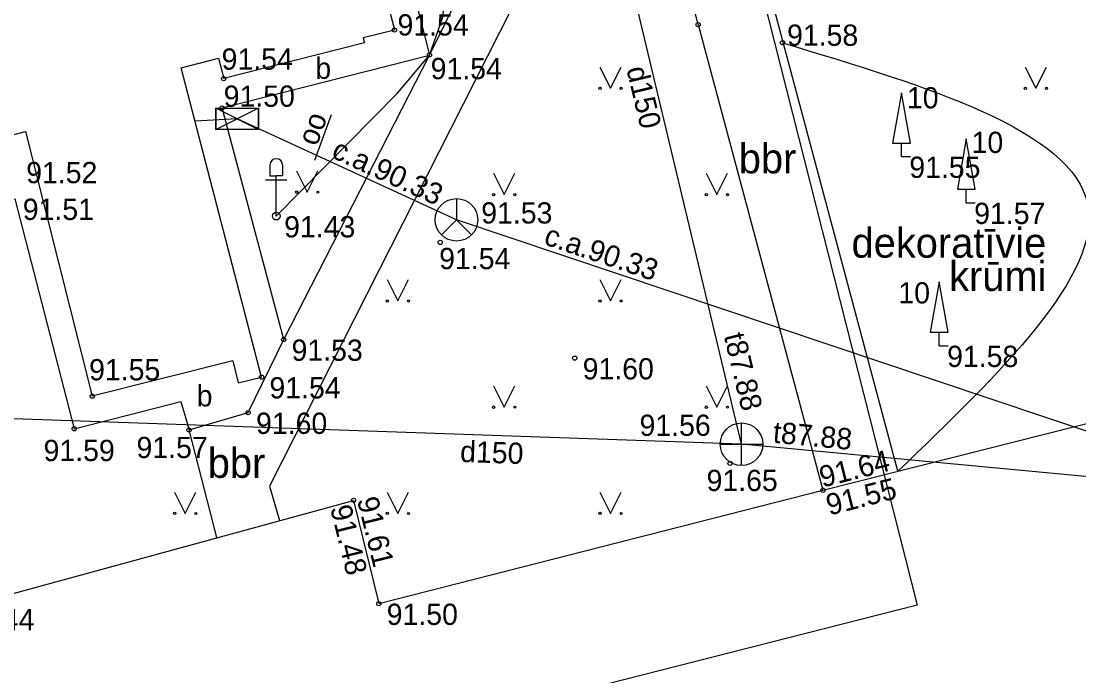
# Model space of a CAD drawing. Extents: x 634272 to 634544, y 247463 to 247653.
# Drawn here: x 634418.64 to 634443.51, y 247553.68 to 247569.08 of the extents above; entities that cross this region are included whole.
import ezdxf

# ---------------------------------------------------------------- set-up
doc = ezdxf.new("R2010")
doc.units = 0
for name, color, linetype in [('APGS_ELEM_####_####_#', 7, 'Continuous'), ('APGS_VADP_ZSPR_####_#', 7, 'Continuous'), ('BUVE_BDET_####_####_#', 7, 'Continuous'), ('BUVE_BDET_####_TKST_#', 7, 'Continuous'), ('BUVE_EKAS_####_####_#', 7, 'Continuous'), ('CELI_CAPM_####_####_#', 7, 'Continuous'), ('CELI_CMAL_####_####_#', 7, 'Continuous'), ('CELI_CSEG_####_TKST_#', 7, 'Continuous'), ('RELJ_AATZ_####_TKST_#', 7, 'Continuous'), ('RELJ_ELEM_####_####_#', 7, 'Continuous'), ('ROBZ_UZMR_####_####_#', 7, 'Continuous'), ('SAKK_ELEM_####_####_#', 7, 'Continuous'), ('SAKK_ELEM_####_TKST_#', 7, 'Continuous'), ('SAKK_IZVK_####_TKST_#', 7, 'Continuous'), ('SAKK_KKAN_####_####_#', 7, 'Continuous'), ('SAKK_KKAN_####_TKST_#', 7, 'Continuous'), ('SAKT_ELEM_####_####_#', 7, 'Continuous'), ('SKAN_ELEM_####_####_#', 7, 'Continuous'), ('SKAN_ELEM_PAST_TKST_#', 7, 'Continuous'), ('SKAN_VADP_PAST_####_#', 7, 'Continuous'), ('SKAN_VADP_PAST_TKST_#', 7, 'Continuous'), ('TERT_DIAM_####_TKST_#', 7, 'Continuous'), ('TERT_ELEM_####_####_#', 7, 'Continuous'), ('TERT_IZMT_####_TKST_#', 7, 'Continuous'), ('TERT_KONT_####_####_#', 7, 'Continuous')]:
    doc.layers.add(name, color=color, linetype=linetype)

msp = doc.modelspace()

# ---------------------------------------------------------------- linework, layer by layer
at = {"layer": 'APGS_ELEM_####_####_#'}
for p, q in [((634424.49, 247565.693), (634424.49, 247565.443)), ((634424.79, 247565.693), (634424.79, 247565.443)), ((634424.39, 247565.343), (634424.89, 247565.343)), ((634424.49, 247565.443), (634424.64, 247565.443)), ((634424.64, 247564.493), (634424.64, 247565.443)), ((634424.79, 247565.443), (634424.64, 247565.443))]:
    msp.add_line(p, q, dxfattribs=at)
msp.add_circle((634424.64, 247564.493), 0.0907, dxfattribs=at)
msp.add_arc((634424.64, 247565.693), 0.15, 0, 180, dxfattribs=at)
at = {"layer": 'APGS_VADP_ZSPR_####_#'}
msp.add_lwpolyline([(634424.64, 247564.493), (634427.489, 247567.387), (634428.243, 247568.282), (634428.556, 247569.174), (634428.62, 247569.734), (634428.349, 247570.951), (634427.518, 247573.97), (634425.055, 247583.293), (634424.177, 247586.368), (634423.255, 247589.552), (634422.487, 247592.599), (634438.755, 247598.02), (634453.341, 247601.325), (634455.217, 247592.645), (634458.049, 247580.186), (634460.842, 247567.679), (634446.181, 247564.209)], dxfattribs=at)
at = {"layer": 'BUVE_BDET_####_####_#'}
msp.add_line((634426.365, 247575.637), (634428.243, 247568.282), dxfattribs=at)
for points in [[(634424.815, 247561.591), (634423.367, 247567.037), (634428.243, 247568.282)], [(634406.216, 247555.83), (634405.003, 247560.603), (634406.24, 247560.87), (634406.454, 247560.126), (634408.225, 247560.507), (634407.669, 247562.916), (634408.905, 247563.238), (634409.092, 247562.484), (634410.939, 247562.975), (634410.684, 247563.745), (634412.053, 247564.132), (634412.297, 247563.275), (634418.496, 247564.903), (634419.89, 247559.492), (634422.401, 247560.131), (634422.592, 247559.464)]]:
    msp.add_lwpolyline(points, dxfattribs=at)
at = {"layer": 'BUVE_EKAS_####_####_#'}
for p, q in [((634427.419, 247568.87), (634426.685, 247568.683)), ((634426.685, 247568.683), (634426.713, 247568.572)), ((634423.281, 247568.211), (634423.405, 247567.727)), ((634423.618, 247561.09), (634420.314, 247560.258)), ((634423.618, 247561.09), (634423.749, 247560.57))]:
    msp.add_line(p, q, dxfattribs=at)
for points in [[(634427.308, 247569.298), (634427.419, 247568.871)], [(634426.713, 247568.572), (634423.405, 247567.727)], [(634422.405, 247567.984), (634423.281, 247568.211)], [(634423.749, 247560.57), (634424.295, 247560.706), (634422.405, 247567.984)], [(634416.138, 247565.805), (634418.747, 247566.484)], [(634418.747, 247566.484), (634420.314, 247560.258)]]:
    msp.add_lwpolyline(points, dxfattribs=at)
at = {"layer": 'CELI_CAPM_####_####_#'}
msp.add_lwpolyline([(634386.18, 247584.245), (634386.517, 247583.098), (634389.042, 247573.196), (634391.897, 247562.219), (634393.7, 247555.164), (634394.221, 247554.237), (634394.857, 247553.225), (634395.836, 247552.623), (634399.496, 247551.073), (634400.928, 247550.806), (634417.097, 247555.253), (634426.457, 247557.809), (634427.052, 247555.379), (634437.491, 247558.047), (634462.278, 247564.311)], dxfattribs=at)
at = {"layer": 'CELI_CMAL_####_####_#'}
for points in [[(634439.253, 247558.492), (634434.43, 247576.565)], [(634433.022, 247575.005), (634424.481, 247558.139), (634424.716, 247557.334)], [(634434.559, 247568.999), (634433.022, 247575.005)], [(634423.98, 247559.871), (634424.815, 247561.591), (634428.243, 247568.282), (634430.939, 247573.736)], [(634434.559, 247568.999), (634437.491, 247558.047)], [(634422.592, 247559.464), (634423.98, 247559.871)], [(634423.244, 247556.932), (634422.592, 247559.464)]]:
    msp.add_lwpolyline(points, dxfattribs=at)
at = {"layer": 'RELJ_ELEM_####_####_#'}
for centre in [(634434.559, 247568.999), (634427.419, 247568.871), (634436.545, 247568.569), (634428.243, 247568.282), (634423.405, 247567.727), (634423.367, 247567.037), (634428.495, 247563.875), (634424.815, 247561.591), (634431.659, 247561.153), (634424.295, 247560.706), (634420.314, 247560.258), (634423.98, 247559.871), (634419.89, 247559.492), (634422.592, 247559.464), (634435.31, 247558.68), (634437.491, 247558.047), (634426.457, 247557.809), (634427.052, 247555.379)]:
    msp.add_circle(centre, 0.05, dxfattribs=at)
at = {"layer": 'ROBZ_UZMR_####_####_#'}
for points in [[(634428.96, 247597.768), (634439.705, 247555.341)], [(634439.705, 247555.341), (634428.904, 247552.595)]]:
    msp.add_lwpolyline(points, dxfattribs=at)
at = {"layer": 'SAKK_ELEM_####_####_#'}
msp.add_line((634428.878, 247564.406), (634429.232, 247564.052), dxfattribs=at)
msp.add_lwpolyline([(634428.878, 247564.906), (634428.878, 247564.406), (634428.524, 247564.052)], dxfattribs=at)
msp.add_circle((634428.878, 247564.406), 0.5, dxfattribs=at)
at = {"layer": 'SAKK_IZVK_####_TKST_#'}
msp.add_line((634425.549, 247565.811), (634425.942, 247566.887), dxfattribs=at)
at = {"layer": 'SAKK_KKAN_####_####_#'}
for points in [[(634428.878, 247564.406), (634423.723, 247566.783), (634422.732, 247566.726)], [(634466.565, 247551.758), (634428.878, 247564.406)]]:
    msp.add_lwpolyline(points, dxfattribs=at)
at = {"layer": 'SAKT_ELEM_####_####_#'}
msp.add_lwpolyline([(634423.223, 247567.033), (634424.223, 247567.033), (634424.223, 247566.533), (634423.223, 247566.533)], close=True, dxfattribs=at)
for points in [[(634423.723, 247566.783), (634423.223, 247567.033), (634423.223, 247566.533), (634423.723, 247566.783)], [(634423.723, 247566.783), (634424.223, 247566.533), (634424.223, 247567.033), (634423.723, 247566.783)]]:
    msp.add_lwpolyline(points, dxfattribs=at)
at = {"layer": 'SKAN_ELEM_####_####_#'}
for p, q in [((634435.579, 247558.628), (634435.579, 247559.628)), ((634435.079, 247559.128), (634436.079, 247559.128))]:
    msp.add_line(p, q, dxfattribs=at)
msp.add_circle((634435.579, 247559.128), 0.5, dxfattribs=at)
at = {"layer": 'SKAN_VADP_PAST_####_#'}
for points in [[(634467.293, 247556.065), (634460.247, 247556.807), (634435.579, 247559.128), (634432.448, 247572.232), (634426.846, 247593.259), (634423.583, 247606.965), (634413.214, 247604.726), (634403.305, 247602.476), (634405.576, 247593.489), (634409.131, 247581.899)], [(634435.579, 247559.128), (634414.627, 247559.859), (634413.306, 247565.067)]]:
    msp.add_lwpolyline(points, dxfattribs=at)
at = {"layer": 'TERT_ELEM_####_####_#'}
for p, q in [((634432.25, 247568), (634432.5, 247567.5)), ((634432.5, 247567.5), (634432.75, 247568)), ((634442.25, 247568), (634442.5, 247567.5)), ((634442.5, 247567.5), (634442.75, 247568)), ((634439.338, 247565.893), (634439.338, 247566.213)), ((634439.338, 247565.893), (634439.548, 247565.893)), ((634425.119, 247565.557), (634425.369, 247565.057)), ((634425.369, 247565.057), (634425.619, 247565.557)), ((634429.75, 247565.5), (634430, 247565)), ((634430, 247565), (634430.25, 247565.5)), ((634434.75, 247565.5), (634435, 247565)), ((634435, 247565), (634435.25, 247565.5)), ((634440.863, 247564.808), (634440.863, 247565.128)), ((634440.863, 247564.808), (634441.073, 247564.808)), ((634427.25, 247563), (634427.5, 247562.5)), ((634427.5, 247562.5), (634427.75, 247563)), ((634432.25, 247563), (634432.5, 247562.5)), ((634432.5, 247562.5), (634432.75, 247563)), ((634440.227, 247561.445), (634440.227, 247561.765)), ((634440.227, 247561.445), (634440.437, 247561.445)), ((634429.75, 247560.5), (634430, 247560)), ((634430, 247560), (634430.25, 247560.5)), ((634434.75, 247560.5), (634435, 247560)), ((634435, 247560), (634435.25, 247560.5)), ((634422.25, 247558), (634422.5, 247557.5)), ((634422.5, 247557.5), (634422.75, 247558)), ((634427.25, 247558), (634427.5, 247557.5)), ((634427.5, 247557.5), (634427.75, 247558)), ((634432.25, 247558), (634432.5, 247557.5)), ((634432.5, 247557.5), (634432.75, 247558))]:
    msp.add_line(p, q, dxfattribs=at)
for points in [[(634439.128, 247566.213), (634439.548, 247566.213), (634439.338, 247567.393)], [(634440.653, 247565.128), (634441.073, 247565.128), (634440.863, 247566.308)], [(634440.017, 247561.765), (634440.437, 247561.765), (634440.227, 247562.945)]]:
    msp.add_lwpolyline(points, close=True, dxfattribs=at)
for centre, radius in [((634432.25, 247567.5), 0.028), ((634432.75, 247567.5), 0.0263), ((634442.25, 247567.5), 0.028), ((634442.75, 247567.5), 0.0263), ((634425.119, 247565.057), 0.028), ((634425.619, 247565.057), 0.0263), ((634429.75, 247565), 0.028), ((634430.25, 247565), 0.0263), ((634434.75, 247565), 0.028), ((634435.25, 247565), 0.0263), ((634427.25, 247562.5), 0.028), ((634427.75, 247562.5), 0.0263), ((634432.25, 247562.5), 0.028), ((634432.75, 247562.5), 0.0263), ((634429.75, 247560), 0.028), ((634430.25, 247560), 0.0263), ((634434.75, 247560), 0.028), ((634435.25, 247560), 0.0263), ((634422.25, 247557.5), 0.028), ((634422.75, 247557.5), 0.0263), ((634427.25, 247557.5), 0.028), ((634427.75, 247557.5), 0.0263), ((634432.25, 247557.5), 0.028), ((634432.75, 247557.5), 0.0263)]:
    msp.add_circle(centre, radius, dxfattribs=at)
at = {"layer": 'TERT_KONT_####_####_#'}
msp.add_spline([(634436.545, 247568.569), (634443.717, 247564.77), (634439.253, 247558.492)], degree=3, dxfattribs=at)

# ---------------------------------------------------------------- texts
at = {"layer": 'BUVE_BDET_####_TKST_#'}
for p in [(634425.56, 247567.721), (634422.771, 247560.018)]:
    msp.add_text('b', height=0.5, dxfattribs=at).set_placement(p)
at = {"layer": 'CELI_CSEG_####_TKST_#'}
for p in [(634435.515, 247565.5), (634423.03, 247558.338)]:
    msp.add_text('bbr', height=0.7, dxfattribs=at).set_placement(p)
at = {"layer": 'RELJ_AATZ_####_TKST_#'}
for s, p in [(' 91.54', (634427.306, 247568.741)), (' 91.58', (634436.464, 247568.499)), (' 91.54', (634423.171, 247567.937)), (' 91.54', (634428.085, 247567.714)), (' 91.50', (634423.219, 247567.065)), (' 91.52', (634418.576, 247565.268)), (' 91.55', (634439.338, 247565.393)), (' 91.55', (634439.338, 247565.393)), (' 91.51', (634418.496, 247564.403)), (' 91.57', (634440.863, 247564.308)), (' 91.57', (634440.863, 247564.308)), (' 91.43', (634424.64, 247563.993)), (' 91.54', (634428.285, 247563.246)), (' 91.53', (634424.815, 247561.091)), (' 91.58', (634440.227, 247560.945)), (' 91.58', (634440.227, 247560.945)), (' 91.55', (634420.055, 247560.631)), (' 91.60', (634431.659, 247560.653)), (' 91.54', (634424.295, 247560.206)), (' 91.60', (634423.98, 247559.371)), (' 91.57', (634421.17, 247558.802)), (' 91.59', (634418.985, 247558.732)), (' 91.65', (634434.572, 247558.027)), (' 91.50', (634427.052, 247554.879)), (' 91.44', (634417.097, 247554.753))]:
    msp.add_text(s, height=0.5, dxfattribs=at).set_placement(p)
for s, rotation, p in [(' 91.64', 14.1825, (634437.302, 247558.06)), (' 91.55', 14.3368, (634437.463, 247557.402)), (' 91.61', 283.7585, (634426.492, 247558.008)), (' 91.48', 283.7585, (634425.861, 247557.816))]:
    msp.add_text(s, height=0.5, rotation=rotation, dxfattribs=at).set_placement(p)
at = {"layer": 'SAKK_ELEM_####_TKST_#'}
msp.add_text(' 91.53', height=0.5, dxfattribs=at).set_placement((634429.274, 247564.319))
at = {"layer": 'SAKK_IZVK_####_TKST_#'}
msp.add_text('oo', height=0.5, rotation=69.9407, dxfattribs=at).set_placement((634425.593, 247566.119))
at = {"layer": 'SAKK_KKAN_####_TKST_#'}
for rotation, p in [(335.2453, (634425.91, 247565.886)), (341.4479, (634430.905, 247563.839))]:
    msp.add_text('c.a.90.33', height=0.5, rotation=rotation, dxfattribs=at).set_placement(p)
at = {"layer": 'SKAN_ELEM_PAST_TKST_#'}
msp.add_text(' 91.56', height=0.5, dxfattribs=at).set_placement((634432.996, 247559.325))
at = {"layer": 'SKAN_VADP_PAST_TKST_#'}
for s, rotation, p in [('d150', 283.438, (634432.87, 247567.956)), ('t87.88', 283.438, (634435.161, 247561.684)), ('t87.88', 354.6249, (634436.304, 247559.168)), ('d150', 358.0023, (634428.957, 247558.713))]:
    msp.add_text(s, height=0.5, rotation=rotation, dxfattribs=at).set_placement(p)
at = {"layer": 'TERT_DIAM_####_TKST_#'}
for p in [(634439.468, 247567.027), (634440.988, 247565.978), (634439.267, 247562.439)]:
    msp.add_text('10', height=0.5, dxfattribs=at).set_placement(p)
at = {"layer": 'TERT_IZMT_####_TKST_#'}
for s, p in [('dekoratīvie', (634438.166, 247563.516)), ('krūmi', (634440.46, 247562.735))]:
    msp.add_text(s, height=0.7, dxfattribs=at).set_placement(p)

doc.saveas('drawing.dxf')
